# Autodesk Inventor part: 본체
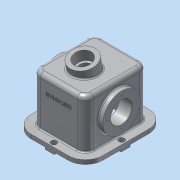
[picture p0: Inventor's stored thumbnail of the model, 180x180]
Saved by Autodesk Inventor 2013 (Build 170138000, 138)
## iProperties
Created: 2014-11
Part Number: 본체
Material: 알루미늄 6061
Document SubType Name: Modeling
Designer: WINDOWS7
Density: 1 g/cm^3
Author: WINDOWS7
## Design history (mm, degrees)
sketch "스케치1"
  geometry: L1 (0, 0)-(130, 0); L2 (130, 0)-(130, 152); L3 (130, 152)-(0, 152); L4 (0, 152)-(0, 0)
  constraints: 8 end point, 2 parallel, 1 horizontal, 1 perpendicular
  dimensions: "d0" = 130 distance of L1.start L1.end; "d1" = 152 distance of L3.end L1.start
extrude "돌출1" new body sketch "스케치1" distance "d2" = 118; taper "d3" = 0 deg
feature "쉘1" dims "d4" = 10
fillet "모깎기1" dims "d5" = 20
fillet "모깎기2" dims "d6" = 10
sketch "스케치2"
  geometry: L1 (-20, 10)-(-110, 10) reference; L2 (-120, 20)-(-120, 132) reference; L3 (-110, 142)-(-20, 142) reference; L4 (-10, 132)-(-10, 20) reference; L5 (-110, 152)-(-20, 152) reference; L6 (-130, 20)-(-130, 132) reference; L7 (22, 174)-(-152, 174); L8 (-152, 174)-(-152, -22); L9 (-152, -22)-(22, -22); L10 (22, -22)-(22, 174); A1 r 10 centre (-110, 20) between (-120, 20) and (-110, 10) reference; A2 r 10 centre (-110, 132) between (-110, 142) and (-120, 132) reference; A3 r 10 centre (-20, 132) between (-10, 132) and (-20, 142) reference; A4 r 10 centre (-20, 20) between (-20, 10) and (-10, 20) reference; 5 further points
  constraints: 8 end point, 4 midpoint, 2 parallel, 1 horizontal, 1 horizontal alignment, 1 perpendicular, 1 vertical alignment
  dimensions: "d7" = 174 distance between parallel lines of L8 L10; "d9" = 196 distance between parallel lines of L7 L9
extrude "돌출2" join sketch "스케치2" distance "d10" = 10; taper "d11" = 0 deg
fillet "모깎기3" dims "d12" = 10
fillet "모깎기4" dims "d13" = 42
sketch "스케치3"
  geometry: L1 (-20, 174)-(-110, 174) reference; L2 (-152, 132)-(-152, 20) reference; L3 (-110, -22)-(-20, -22) reference; L4 (-152, 87)-(-132, 87); L5 (-132, 87)-(-132, 65); L6 (-132, 65)-(-152, 65); L7 (-152, 65)-(-152, 87); L8 (-76, 174)-(-54, 174); L9 (-54, 174)-(-54, 154); L10 (-54, 154)-(-76, 154); L11 (-76, 154)-(-76, 174); 6 further points
  constraints: 16 end point, 6 midpoint, 4 parallel, 2 coincident, 2 horizontal, 2 perpendicular, 1 point on line
  dimensions: "d14" = 20 distance of L5.end L6.end; "d16" = 22 distance of L4.end L5.end; "d20" = 20 distance of L10.end L8.start; "d21" = 22 distance of L9.end L10.end
extrude "돌출3" join sketch "스케치3" distance "d22" = 5; taper "d23" = 0 deg
node "작업 평면1"
node "작업 평면2"
sketch "스케치4"
  geometry: L1 (0, 108)-(90, 108) reference; L2 (34, -10)-(0, -10) reference; 3 further points
  constraints: 1 midpoint, 1 vertical alignment, 1 other
  dimensions: "d24" = 92 distance from line of point (45, 82) L2
feature "엠보싱1" sketch "스케치4" dims "d25" = 1, "d26" = 0
node "작업 평면3"
node "작업 평면4"
sketch "스케치5"
  geometry: L1 (-20, 0)-(-20, 108) reference; L2 (-10, 108)-(-10, -10) reference; L3 (100, -10)-(100, 108) reference; L4 (110, 108)-(110, 0) reference; L5 (-20, 58)-(110, 58); L6 (90, -10)-(0, -10) reference; L7 (-20, 84)-(-32, 84); L8 (-32, 84)-(-32, 103.5); L9 (-32, 103.5)-(-20, 103.5); L10 (-20, 103.5)-(-10, 103.5); L11 (-10, 103.5)-(0, 93.5); L12 (0, 93.5)-(0, 84); L13 (0, 84)-(-20, 84); L14 (45, 58)-(45, -10)
  constraints: 18 end point, 6 perpendicular, 5 point on line, 2 midpoint, 1 parallel
  dimensions: "d27" = 68 distance between parallel lines of L6 L5; "d28" = 32 distance between parallel lines of L12 L8; "d30" = 52 diameter of L13 L5; "d31" = 91 diameter of L9 L5; "d32" = 71 diameter of L11.end L5; "d83" = 10 horizontal distance of L10.end L11.end
revolve "회전1" sketch "스케치5" stored, may be unused: angle "d33" = 90 deg
node "작업 평면5"
sketch "스케치6"
  geometry: C1 r 26 at (0, 0) reference; 1 further point
extrude "돌출4" cut sketch "스케치6" distance "d34" = 322; taper "d35" = 0 deg
node "작업 평면6"
sketch "스케치7"
  geometry: L1 (58, 56)-(169.222, 32.359); L2 (0, 0)-(0, -42) reference; L3 (142.121, 38.12)-(135.675, 7.797); L4 (135.675, 7.797)-(51.555, 25.677); L5 (51.555, 25.677)-(58, 56); C1 r 26 at (58, 56) reference; 1 further point
  constraints: 8 end point, 2 perpendicular, 1 point on line
  dimensions: "d36" = 78 deg angle of L2 L1; "d37" = 86 distance from line of L1.start L3; "d39" = 62 diameter of L4 L1
revolve "회전2" sketch "스케치7" stored, may be unused: angle "d40" = 90 deg
sketch "스케치8"
  geometry: L1 (90, 0)-(0, 0) reference; L2 (0, 132)-(90, 132) reference; L3 (0, 101.5)-(0, 30.5) reference; L4 (-10, 111.5)-(-10, 20.5) reference; L5 (90, 101.5)-(90, 30.5) reference; L6 (100, 20.5)-(100, 111.5) reference; L7 (0, 101.5)-(0, 132); L8 (0, 30.5)-(0, 0); L9 (90, 30.5)-(90, 0); L10 (0, 0)-(90, 0); L11 (90, 30.5)-(90, 132); L12 (90, 132)-(0, 132); L13 (0, 101.5)-(0, 30.5); A1 r 10 centre (0, 122) between (0, 132) and (-10, 122) reference; A2 r 10 centre (0, 10) between (-10, 10) and (0, 0) reference; A3 r 10 centre (90, 10) between (90, 0) and (100, 10) reference; A4 r 10 centre (90, 122) between (100, 122) and (90, 132) reference; 1 further point
  constraints: 14 end point, 4 collinear, 4 tangent, 2 parallel, 1 perpendicular
extrude "돌출5" cut sketch "스케치8" distance "d41" = 322; taper "d42" = 0 deg
hole "구멍1" diameter "d45" = 30; stored, may be unused: countersink angle "d49" = 90 deg, drill point angle "d51" = 118 deg; dims "d43" = 10, "d44" = 10, "d46" = 6, "d47" = 42, "d48" = 25, "d50" = 45
sketch "스케치9"
  geometry: L1 (-22, 20)-(-22, 132) reference; L2 (110, -22)-(20, -22) reference; L3 (152, 132)-(152, 20) reference; L4 (20, 174)-(110, 174) reference; L5 (0, 132)-(0, 20) reference; L6 (110, 152)-(20, 152) reference; L7 (65, 164)-(65, -12); 10 further points
  constraints: 6 midpoint, 3 horizontal alignment, 3 vertical alignment, 2 end point, 1 perpendicular
  dimensions: "d54" = 10 distance from line of L1 point (-12, 76); "d55" = 10 distance from line of L3 point (142, 76); "d56" = 176 distance of L7.end L7.start
hole "구멍2" sketch "스케치9" at (-12, 76), (142, 76), (65, -12), (65, 164) diameter "d57" = 9; stored, may be unused: countersink angle "d61" = 90 deg, drill point angle "d63" = 118 deg; dims "d58" = 6, "d59" = 14, "d60" = 8.6, "d62" = 45
fillet "모깎기5" dims "d64" = 3
fillet "모깎기6" dims "d65" = 3
fillet "모깎기7" dims "d66" = 3
fillet "모깎기8" dims "d67" = 0.3
chamfer "모따기1" distance "d68" = 1; stored, may be unused: second distance "d69" = 2, angle "d70" = 45 deg
sketch "스케치10" dims "d71" = 70
  geometry: C1 r 45.5 at (0, 0) reference; C2 r 27 at (0, 0) reference; 3 further points
  constraints: 2 horizontal alignment, 1 coincident, 2 other
hole "구멍3" sketch "스케치10" at (-35, 0) diameter "d73" = 3.242; stored, may be unused: countersink angle "d77" = 90 deg, drill point angle "d79" = 118 deg; dims "d74" = 13, "d75" = 14, "d76" = 8.6, "d78" = 16
node "작업 평면7"
node "솔리드1"
mirror "대칭1"
mirror "대칭2"
mirror "대칭3"
pattern_circular "원형 패턴1" dims angle "d81" = 360 deg
mirror "대칭4"
node "투영된 루프1"
node "투영된 루프2"
